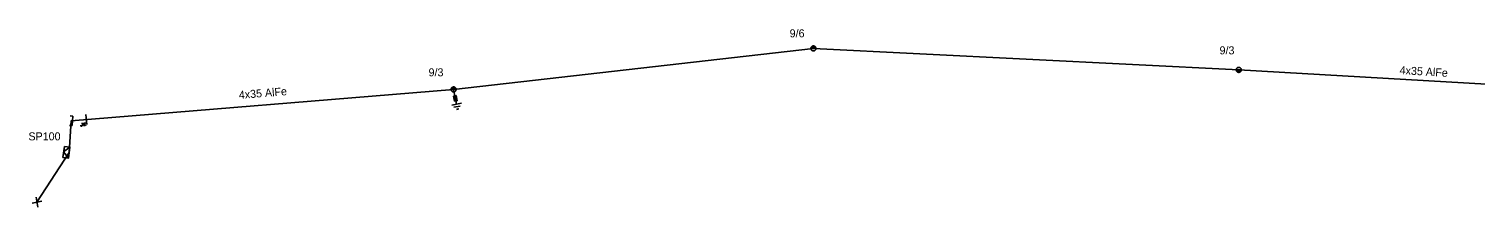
# Model space of a CAD drawing. Extents: x -788458 to -786145, y -1154772 to -1152372.
# Drawn here: x -786781.2 to -786600.5, y -1153561.3 to -1153539 of the extents above; entities that cross this region are included whole.
import ezdxf

# ---------------------------------------------------------------- set-up
doc = ezdxf.new("R2010")
doc.units = 0
for name, color, linetype in [('Vrstva 1', 7, 'Continuous'), ('Vrstva 12', 7, 'Continuous'), ('Vrstva 13', 7, 'Continuous'), ('Vrstva 14', 7, 'Continuous'), ('Vrstva 15', 7, 'Continuous'), ('Vrstva 16', 7, 'Continuous'), ('Vrstva 18', 7, 'Continuous'), ('Vrstva 2', 7, 'Continuous'), ('Vrstva 31', 7, 'Continuous'), ('Vrstva 33', 7, 'Continuous'), ('Vrstva 34', 7, 'Continuous'), ('Vrstva 4', 7, 'Continuous'), ('Vrstva 53', 7, 'Continuous'), ('Vrstva 59', 7, 'Continuous'), ('Vrstva 9', 7, 'Continuous')]:
    doc.layers.add(name, color=color, linetype=linetype)

# ---------------------------------------------------------------- blocks, each defined once
blk = doc.blocks.new('NN440')
at = {"layer": 'Vrstva 2'}
for points in [[(0.63, 0), (0.63, 0.06), (0.62, 0.13), (0.6, 0.19), (0.58, 0.25), (0.55, 0.31), (0.51, 0.37), (0.47, 0.42), (0.42, 0.46), (0.37, 0.51), (0.32, 0.54), (0.26, 0.57), (0.2, 0.59), (0.13, 0.61), (0.07, 0.62), (0, 0.63), (-0.06, 0.62), (-0.13, 0.61), (-0.19, 0.59), (-0.26, 0.57), (-0.31, 0.54), (-0.37, 0.51), (-0.42, 0.46), (-0.47, 0.42), (-0.51, 0.37), (-0.54, 0.31), (-0.57, 0.25), (-0.6, 0.19), (-0.62, 0.13), (-0.63, 0.06), (-0.63, 0), (-0.63, -0.07), (-0.62, -0.14), (-0.6, -0.2), (-0.57, -0.26), (-0.54, -0.32), (-0.51, -0.37), (-0.47, -0.43), (-0.42, -0.47), (-0.37, -0.51), (-0.31, -0.55), (-0.26, -0.58), (-0.19, -0.6), (-0.13, -0.62), (-0.06, -0.63), (0, -0.63), (0.07, -0.63), (0.13, -0.62), (0.2, -0.6), (0.26, -0.58), (0.32, -0.55), (0.37, -0.51), (0.42, -0.47), (0.47, -0.43), (0.51, -0.37), (0.55, -0.32), (0.58, -0.26), (0.6, -0.2), (0.62, -0.14), (0.63, -0.07), (0.63, 0)], [(-0.63, 0), (0.63, 0)], [(-0.6, -0.18), (0.57, -0.18)], [(-0.51, -0.32), (0.5, -0.32)], [(-0.37, -0.47), (0.35, -0.47)]]:
    blk.add_lwpolyline(points, dxfattribs=at)
blk = doc.blocks.new('NN840')
at = {"layer": 'Vrstva 15'}
for points in [[(0, 0.62), (0, -0.63)], [(-0.75, -0.71), (-0.75, -0.66)], [(-0.73, -0.76), (-0.75, -0.71)], [(-0.66, -0.8), (-0.73, -0.76)], [(-0.63, -0.8), (-0.66, -0.8)], [(-0.56, -0.76), (-0.63, -0.8)], [(-0.54, -0.71), (-0.56, -0.76)], [(-0.54, -0.38), (-0.54, -0.71)], [(-0.33, -0.38), (-0.33, -0.8)], [(-0.33, -0.64), (-0.13, -0.38)], [(-0.26, -0.56), (-0.09, -0.8)]]:
    blk.add_lwpolyline(points, dxfattribs=at)
blk = doc.blocks.new('NN800')
at = {"layer": 'Vrstva 1'}
for points in [[(-0.44, 0.44), (0.44, -0.44)], [(-0.44, -0.44), (0.44, 0.44)]]:
    blk.add_lwpolyline(points, dxfattribs=at)
blk = doc.blocks.new('NN820')
at = {"layer": 'Vrstva 13'}
for points in [[(0, 0), (0, -1.05)], [(-0.16, -0.81), (0.16, -0.81)], [(-0.16, -1.47), (-0.16, -0.81)], [(0.16, -1.47), (-0.16, -1.47)], [(0, -1.05), (-0.06, -0.93)], [(0, -1.05), (0.06, -0.93)], [(0, -1.47), (0, -1.87)], [(0.16, -0.81), (0.16, -1.47)]]:
    blk.add_lwpolyline(points, dxfattribs=at)
blk = doc.blocks.new('NN630')
at = {"layer": 'Vrstva 9'}
for points in [[(0, -0.7), (-0.7, 0)], [(-0.7, -0.7), (-0.7, 0), (0.7, 0), (0.7, -0.7)], [(-0.7, -0.7), (0.7, -0.7)], [(0, -0.7), (0.7, 0)]]:
    blk.add_lwpolyline(points, dxfattribs=at)
blk = doc.blocks.new('NN810')
at = {"layer": 'Vrstva 14'}
for points in [[(0, -0.64), (0, -1.89)], [(0.63, -1.89), (-0.62, -1.89)], [(0.39, -2.2), (-0.4, -2.2)], [(0, -2.52), (-0.12, -2.52)], [(0.14, -2.52), (0, -2.52)]]:
    blk.add_lwpolyline(points, dxfattribs=at)
blk = doc.blocks.new('NN515')
at = {"layer": 'Vrstva 2'}
for points in [[(-0.59, 0.18), (0.59, 0.18)], [(-0.59, 0.18), (-0.59, -0.18)], [(0.59, 0.18), (0.59, -0.18)]]:
    blk.add_lwpolyline(points, dxfattribs=at)

msp = doc.modelspace()

# ---------------------------------------------------------------- linework, layer by layer
at = {"layer": 'Vrstva 4'}
msp.add_lwpolyline([(-786583.29, -1153546.79), (-786630.06, -1153544.09), (-786683.21, -1153541.41), (-786728.17, -1153546.54), (-786775.96, -1153550.46), (-786776.21, -1153554.45)], dxfattribs=at)
at = {"layer": 'Vrstva 59'}
msp.add_lwpolyline([(-786776.21, -1153554.45), (-786780.24, -1153560.65)], dxfattribs=at)

# ---------------------------------------------------------------- block references
at = {"layer": 'Vrstva 13'}
for p, xscale, yscale, rotation in [((-786683.21, -1153541.41), 0.49999999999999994, 0.4999999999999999, -174.54843606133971), ((-786630.06, -1153544.09), 0.49999999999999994, 0.5, -2.5186417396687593), ((-786728.17, -1153546.54), 0.5000000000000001, 0.4999999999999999, -174.5484360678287)]:
    msp.add_blockref('NN440', p, dxfattribs=dict(at, xscale=xscale, yscale=yscale, rotation=rotation))
at = {"layer": 'Vrstva 13', "rotation": -93.80422502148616}
msp.add_blockref('NN515', (-786775.96, -1153550.46), dxfattribs=at)
at = {"layer": 'Vrstva 15', "rotation": 11.310035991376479}
msp.add_blockref('NN810', (-786728.17, -1153546.54), dxfattribs=at)
at = {"layer": 'Vrstva 16', "rotation": 11.243688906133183}
msp.add_blockref('NN820', (-786728.17, -1153546.54), dxfattribs=at)
at = {"layer": 'Vrstva 18', "rotation": 4.689218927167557}
msp.add_blockref('NN840', (-786774.07, -1153550.3), dxfattribs=at)
at = {"layer": 'Vrstva 31', "rotation": -97.52992676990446}
msp.add_blockref('NN630', (-786776.21, -1153554.45), dxfattribs=at)
at = {"layer": 'Vrstva 34', "rotation": 55.5303362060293}
msp.add_blockref('NN800', (-786780.24, -1153560.65), dxfattribs=at)

# ---------------------------------------------------------------- texts
at = {"layer": 'Vrstva 12'}
for s, p in [('9/6', (-786686.18, -1153540.02)), ('9/3', (-786632.46, -1153542.15)), ('9/3', (-786731.3, -1153544.9))]:
    msp.add_text(s, height=1, dxfattribs=at).set_placement(p)
at = {"layer": 'Vrstva 33'}
msp.add_text('SP100', height=1, dxfattribs=at).set_placement((-786781.3, -1153552.91))
at = {"layer": 'Vrstva 53'}
for rotation, p in [(356.696, (-786609.98, -1153544.62)), (4.689, (-786754.97, -1153547.74))]:
    msp.add_text('4x35 AlFe', height=1, rotation=rotation, dxfattribs=at).set_placement(p)

doc.saveas('drawing.dxf')
